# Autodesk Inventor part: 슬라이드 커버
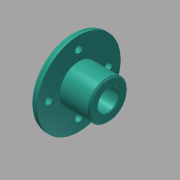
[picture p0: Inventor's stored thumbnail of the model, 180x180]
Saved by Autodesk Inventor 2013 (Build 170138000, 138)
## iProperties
Created: 2015-12
Part Number: 슬라이드 커버
Document SubType Name: Modeling
Designer: mdu
Density: 2.71 g/cm^3
Material: 알루미늄 6061
Mass: 49.5723 g
Surface Area: 80.7135 cm^2
Volume: 18.2924 cm^3
Author: mdu
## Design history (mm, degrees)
sketch "스케치1"
  geometry: L1 (-12.5, 0)-(12.5, 0); L2 (-12.5, 0)-(-12.5, 28); L3 (-12.5, 28)-(-7.5, 28); L4 (-7.5, 28)-(-7.5, 13); L5 (-7.5, 13)-(12.5, 13); L6 (12.5, 13)-(12.5, 0); 2 further points
  constraints: 12 end point, 3 perpendicular, 1 coincident, 1 horizontal, 1 midpoint, 1 parallel
  dimensions: "d1" = 56 diameter of L3 L1; "d2" = 26 diameter of L5 L1; "d5" = 5 distance of L2.end L3.end; "d32" = 20 distance of L4.end L5.end
revolve "회전1" sketch "스케치1" stored, may be unused: angle "d6" = 90 deg
sketch "스케치2" dims "d33" = 40
  geometry: 3 further points
  constraints: 2 vertical alignment, 1 coincident, 2 other
hole "구멍1" sketch "스케치2" at (0, 20) diameter "d8" = 5; stored, may be unused: countersink angle "d12" = 90 deg, drill point angle "d14" = 118 deg; dims "d9" = 6, "d10" = 8, "d11" = 4.4, "d13" = 8
hole "구멍2" diameter "d20" = 14; stored, may be unused: countersink angle "d24" = 90 deg, drill point angle "d26" = 0 deg; dims "d18" = 10, "d19" = 10, "d21" = 6, "d22" = 8, "d23" = 4.4, "d25" = 8
fillet "모깎기1" dims "d27" = 3
chamfer "모따기1" distance "d29" = 1; stored, may be unused: second distance "d30" = 2, angle "d31" = 45 deg
chamfer "모따기2" distance "d35" = 0.5; stored, may be unused: second distance "d36" = 2, angle "d37" = 45 deg
node "솔리드1"
pattern_circular "원형 패턴1" dims angle "d16" = 360 deg
